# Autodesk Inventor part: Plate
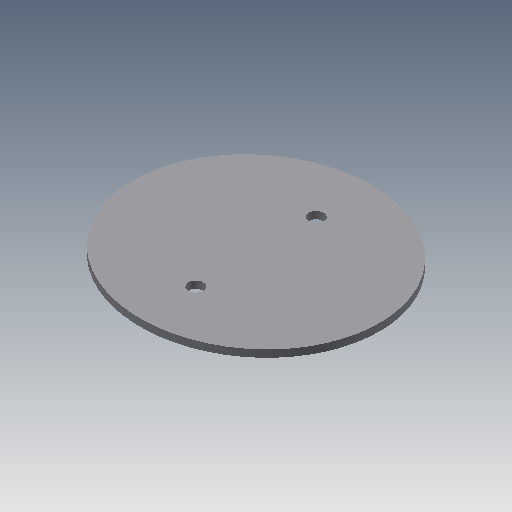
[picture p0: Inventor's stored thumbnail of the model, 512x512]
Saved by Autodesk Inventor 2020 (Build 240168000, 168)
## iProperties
Created: 2009-04
Part Number: Plate
Document SubType Name: Modeling
Designer: Sham
Density: 1 g/cm^3
Material: Generic
Appearance: Default
Author: Sham
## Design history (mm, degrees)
sketch "Sketch1"
  geometry: C1 r 6.25 at (-50, 0); C2 r 6.25 at (50, 0); 4 further points
  constraints: 2 centre point, 1 coincident, 5 other
  dimensions: "d1" = 12.5 diameter of C1; "d2" = 12.5 diameter of C2; "d3" = 100 distance of C2.centre C1.centre; "d4" = 102.5 distance of point (0, 0) point (0, 102.5); "d5" = 96 distance of point (0, 0) point (-96, 0); "d6" = 50 distance of point (0, 0) C1.centre
extrude "Extrusion1" new body sketch "Sketch1" distance "d7" = 6; taper "d8" = 0 deg
body "Solid1"
